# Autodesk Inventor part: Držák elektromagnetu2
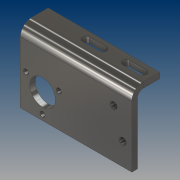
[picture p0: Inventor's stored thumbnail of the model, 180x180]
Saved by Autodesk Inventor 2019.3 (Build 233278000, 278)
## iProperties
Created: 2019-04
Part Number: Držák elektromagnetu2
Material: Ocel, měkká
Document SubType Name: Plech
Designer: B-hon
Density: 7.85 g/cm^3
Sheet Metal Rule: Výchozí_mm
Appearance: Ocel – leštěná
Author: B-hon
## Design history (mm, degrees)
node "Plocha1"
  sketch "Náčrt1"
    geometry: L1 (0, 0)-(100, 0); L2 (100, 0)-(100, 65); L3 (100, 65)-(0, 65); L4 (0, 65)-(0, 0)
    constraints: 8 end point, 2 parallel, 1 horizontal, 1 perpendicular
    dimensions: "d0" = 100 distance of L3.end L2.end; "d1" = 65 distance of L2.end L1.end
node "Obruba1"
sketch "Náčrt3"
  geometry: L1 (0, 65)-(100, 65) reference; L2 (0, 0)-(0, 55) reference; 1 further point
  dimensions: "d13" = 43 distance from line of L1 point (20, 22); "d14" = 20 distance from line of L2 point (20, 22)
hole "Díra1" sketch "Náčrt3" at (20, 22) diameter "d15" = 23; stored, may be unused: countersink angle "d19" = 90 deg, drill point angle "d21" = 118 deg; dims "d16" = 12, "d17" = 6, "d18" = 2, "d20" = 5 (= Tloušťka)
sketch "Náčrt4"
  geometry: L1 (122.192, -13.73)-(40, -13.73); L2 (40, -13.73)-(40, 50); L3 (40, 50)-(122.192, 50); L4 (122.192, 50)-(122.192, -13.73); L5 (100, 55)-(100, 0) reference; L6 (100, 55)-(0, 55) reference; 1 further point
  constraints: 8 end point, 2 parallel, 1 horizontal, 1 perpendicular
  dimensions: "d22" = 60 distance between parallel lines of L2 L5; "d23" = 5 distance between parallel lines of L6 L3
extrude "Vysunutí1" cut sketch "Náčrt4" distance "d24" = 10; taper "d25" = 0 deg
sketch "Náčrt6"
  geometry: L1 (92.5, -7.5)-(77.5, -7.5); L2 (92.5, -4.25)-(77.5, -4.25); L3 (77.5, -10.75)-(92.5, -10.75); L4 (41.5, -7.5)-(56.5, -7.5); L5 (41.5, -10.75)-(56.5, -10.75); L6 (56.5, -4.25)-(41.5, -4.25); L7 (0, 0)-(100, 0) reference; L8 (100, 0)-(100, -15) reference; A1 r 3.25 centre (92.5, -7.5) between (92.5, -10.75) and (92.5, -4.25); A2 r 3.25 centre (77.5, -7.5) between (77.5, -4.25) and (77.5, -10.75); A3 r 3.25 centre (41.5, -7.5) between (41.5, -4.25) and (41.5, -10.75); A4 r 3.25 centre (56.5, -7.5) between (56.5, -10.75) and (56.5, -4.25); 3 further points
  constraints: 16 end point, 8 point on circle, 8 tangent, 4 centre point, 2 midpoint, 2 parallel, 2 point on line, 1 horizontal
  dimensions: "d33" = 6.5 diameter of A2; "d34" = 6.5 diameter of A4; "d35" = 15 distance of L2.start L2.end; "d36" = 15 distance of L6.start L6.end (= d35); "d37" = 7.5 distance from line of L7 point (85, -7.5); "d38" = 15 distance from line of L8 point (85, -7.5); "d39" = 36 distance of point (49, -7.5) point (85, -7.5)
extrude "Vysunutí3" cut sketch "Náčrt6" distance "d40" = 10; taper "d41" = 0 deg
sketch "Náčrt7" dims "d42" = 34
  geometry: C1 r 11.5 at (20, 22) reference; 3 further points
  constraints: 1 coincident, 1 vertical alignment, 2 other
hole "Díra2" sketch "Náčrt7" at (20, 5) diameter "d43" = 4.5; stored, may be unused: countersink angle "d47" = 90 deg, drill point angle "d49" = 118 deg; dims "d44" = 6, "d45" = 4, "d46" = 2, "d48" = 5 (= Tloušťka)
pattern_circular "Kruhové pole1" dims angle "d51" = 360 deg
node "Upravit přímo1"
sketch "Náčrt8"
  geometry: L1 (100, 0)-(100, 55) reference; L2 (100, 0)-(0, 0) reference; 1 further point
  dimensions: "d59" = 8 distance from line of L1 point (92, 20); "d60" = 20 distance from line of L2 point (92, 20)
hole "Díra3" sketch "Náčrt8" at (92, 20) diameter "d61" = 6; stored, may be unused: countersink angle "d65" = 90 deg, drill point angle "d67" = 118 deg; dims "d62" = 6, "d63" = 4, "d64" = 2, "d66" = 5 (= Tloušťka)
sketch "Náčrt9" dims "d68" = 50
  geometry: C1 r 3 at (92, 20) reference; 3 further points
  constraints: 1 coincident, 3 other
hole "Díra4" sketch "Náčrt9" at (83.861, 43.638) diameter "d70" = 6; stored, may be unused: countersink angle "d74" = 90 deg, drill point angle "d76" = 118 deg; dims "d71" = 6, "d72" = 4, "d73" = 2, "d75" = 5 (= Tloušťka)
node "Těleso1"
feature "Deska1" dims "d2" = 5 (= Tloušťka)
sketch "Náčrt2"
  geometry: L1 through (50, 0) direction (-1, 0); L2 through (0, -12.5) direction (0, -1); L3 (0, -25)-(100, -25); L4 (100, -25)-(100, 0)
  constraints: 6 end point, 1 horizontal, 1 perpendicular, 1 vertical
feature "Deska2" dims "d2" = 5 (= Tloušťka), "d3" = 5 (= ŠířkaVýštipu), "d4" = 2.5 (= HloubkaVýštipu), "d5" = 10 (= MinimálníZbytek), "d6" = 5 (= PřechodovýPoloměr), "d7" = 25, "d8" = 90 deg, "d9" = 5 (= PoloměrOhybu), "d10" = 20 (= VelikostRohovéhoVýštipu), "d11" = 5 (= VelikostMezery), "d12" = 5 (= VelikostJacobihoPoloměru), "MezeraVystřižení" = 0.01
feature "Ohyb1" dims "d2" = 5 (= Tloušťka), "d3" = 5 (= ŠířkaVýštipu), "d4" = 2.5 (= HloubkaVýštipu), "d5" = 10 (= MinimálníZbytek), "d6" = 5 (= PřechodovýPoloměr), "d7" = 25, "d8" = 90 deg, "d9" = 5 (= PoloměrOhybu), "MezeraVystřižení" = 0.01
feature "Roh1" dims "d7" = 25, "d8" = 90 deg, "d10" = 20 (= VelikostRohovéhoVýštipu), "d11" = 5 (= VelikostMezery), "d12" = 5 (= VelikostJacobihoPoloměru)
feature "Posunout1" dims "d55" = 60
other parameters: "Tloušťka" = 5 (derived), "KSoučinitel" = 4.4, "PoloměrOhybu" = 5 (= Tloušťka), "ŠířkaVýštipu" = 5 (= Tloušťka), "HloubkaVýštipu" = 2.5 (= 0.5 x Tloušťka), "PřechodovýPoloměr" = 5 (= PoloměrOhybu), "VelikostJacobihoPoloměru" = 5 (= PoloměrOhybu), "VelikostMezery" = 5 (= Tloušťka), "d53" = 0, "d54" = 0
